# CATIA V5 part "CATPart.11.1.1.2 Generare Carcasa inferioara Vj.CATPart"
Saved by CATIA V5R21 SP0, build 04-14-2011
Part number: Carcasa inferioara VJ I
Bounding box of the stored display mesh (mm): x -120 to 120, y -20 to 190, z -98 to 38
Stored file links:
  C:\Users\MIRCEA\Desktop\MOM\Mogan\model\CATPart.11.1.1.2 Generare Carcasa inferioara Vj.CATPart
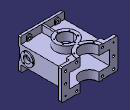
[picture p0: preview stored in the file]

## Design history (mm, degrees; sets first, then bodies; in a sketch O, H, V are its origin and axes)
Parameters
  aw = 100 mm
  a = 90 mm
  Lg = 60 mm
  L1 = 85 mm
  L2 = 75 mm
  Rf1 = 46 mm
  Rr1 = 31 mm
  Rf2 = 55 mm
  Rr2 = 40 mm
  gf1 = 12 mm
  gf2 = 15 mm
  gp = 8 mm
  Lf1 = 35 mm
  Lf = 35 mm
Sketch1 on face of Pad1 from Sketch2.L11, origin (0, -10, 2.4007), H (-1, 0, 0), V (0, 0, 1)
  point P1 (70.0496, -70.1533)
  line L1 (70.0496, -70.1533) -> (50.0496, -70.1533)
  line L2 (70.0496, -70.1533) -> (70.0496, -83.9084)
  point P4 (70.0496, -85.1533)
  line L3 (50.0496, -70.1533) -> (50.0496, -83.9084)
  arc A1 centre (60.0496, -83.9084) radius 10 from (50.0496, -83.9084) to (70.0496, -83.9084) ccw
  line L4 (70.0496, 5.8467) -> (50.0496, 5.8467)
  point P8 (50.0496, 5.8467)
  line L5 (50.0496, 5.8467) -> (50.0496, 19.1827)
  point P9 (50.0496, 20.8467)
  line L6 (70.0496, 5.8467) -> (70.0496, 19.1827)
  arc A2 centre (60.0496, 19.1827) radius 10 from (70.0496, 19.1827) to (50.0496, 19.1827) ccw
  distance P1 P4 = 15
  radius A1 = 10
  distance P8 P9 = 15
  radius A2 = 10
  horizontal: L1 H, L4 H
  vertical: L2 V, L3 V, L5 V, L6 V
  coincidence: L2 P4, P8 L3, L5 P9
  tangency: A1 L3, A1 L2, A2 L6, A2 L5
Sketch2 on yz-plane, origin (0, 0, 0), H (0, 1, 0), V (0, 0, 1)
  point P1 (0, -68)
  line L1 (0, -68) -> (0, 8)
  line L2 (0, 8) -> (-10, 8)
  line L3 (-10, 8) -> (-10, 38)
  line L4 (-10, 38) -> (-20, 38)
  line L5 (-20, 38) -> (-20, -2)
  line L6 (-20, -2) -> (-17, -5)
  line L7 (-17, -5) -> (-17, -55)
  line L8 (-17, -55) -> (-20, -58)
  point P9 (-20, -58)
  line L9 (-20, -58) -> (-20, -98)
  line L10 (-20, -98) -> (-10, -98)
  point P11 (-10, -98)
  line L11 (-10, -98) -> (-10, -68)
  line L12 (-10, -68) -> (0, -68)
  reference intersected line E1 through (0, 0) direction (-1, 0) from xy-plane
  reference intersected line E2 through (0, -30) direction (-1, 0) from Plane1
  reference intersected line E3 through (0, -30) direction (-1, 0) from Plane1
  reference intersected line E4 through (0, -30) direction (-1, 0) from Plane1
  distance L4 L10 = 136 {= Lg + 2*Lf + 6 mm}
  distance L5 L3 = 10
  distance L3 L1 = 10
  distance L7 L5 = 3
  angle L5 L6 = 45
  length L7 = 50
  distance E1 L2 = 8 {= gp}
  coincidence: P1 V, P9 L5, P11 L3
  vertical: L1 V, L3 V, L5 V, L7 V, L9 V, L11 V
  horizontal: L2 H, L4 H, L10 H, L12 H
  symmetry: L12 L2 E2, L4 L10 E3, L8 L6 E4
Pad1 "Talpa": profile Sketch2, direction (1, 0, 0), length 93 {= L1 +gp}, mirrored extent
Set1
  Plane1: type Offset, RefPlane start face of Pad2, Offset 30 {= Lg /2}, reversed
  Plane2: type Offset, RefPlane zx-plane, Offset 190 {= aw+a}
  DatumCurve1
  DatumCurve2
  Sketch3, origin (-120, 217, -71), H (0, 0, -1), V (-1, 0, 0), geometry linked from another document
  DatumCurve3 to DatumCurve8
  DatumSurface1
Body1 (main body)
  Sketch4 on xy-plane, origin (0, 0, 0), H (1, 0, 0), V (0, 1, 0)
    line L1 (85, 190) -> (85, 0)
    point P1 (85, 0)
    line L2 (85, 0) -> (-85, 0)
    circle A1 centre (0, 90) radius 31
    point P2 (0, 90)
    arc A2 centre (0, 190) radius 40 from (-40, 190) to (40, 190) ccw
    point P4 (0, 190)
    line L3 (-85, 0) -> (-85, 190)
    line L4 (-85, 190) -> (-40, 190)
    point P6 (-40, 190)
    line L5 (85, 190) -> (40, 190)
    point P7 (40, 190)
    point P8 (-40, 190)
    point P9 (40, 190)
    construction line L6 (0, 90) -> (0, 190)
    distance P2 L2 = 90 {= a}
    radius A1 = 31 {= Rr1}
    distance P4 L1 = 85 {= L1}
    radius A2 = 40 {= Rr2}
    distance P2 P4 = 100 {= aw}
    coincidence: P1 H, P6 A2, P7 A2, L5 P9, L4 P8, L4 L5, L4 P4
    vertical: L1 V, L3 V, L6 V
    horizontal: L2 H, L4 H, L5 H
    equidistance: L3 L1 P2
    symmetry: L3 L1 V
  Pad2 "Perete lateral": profile Sketch4, direction (0, 0, 1), length 8 {= gp}
  Mirror1: of the body so far, about Plane1
  Sketch5 on zx-plane, origin (0, 0, 0), H (-1, 0, 0), V (0, 0, 1)
    point P1 (85, 8)
    line L1 (85, 8) -> (93, 8)
    line L2 (93, 8) -> (93, -68)
    line L3 (93, -68) -> (85, -68)
    line L4 (85, -68) -> (85, 8)
    point P2 (93, 8)
    point P3 (93, -68)
    point P4 (85, -68)
    reference intersected line E1 through (0, 0) direction (0, -1) from yz-plane
    reference intersected line E2 through (0, 0) direction (-1, 0) from xy-plane
    reference intersected line E3 through (0, -30) direction (-1, 0) from Plane1
    reference intersected line E4 through (0, 0) direction (0, -1) from yz-plane
    point P7 (-85, 8)
    point P8 (-93, 8)
    point P9 (-93, -68)
    point P10 (-85, -68)
    line L5 (-85, 8) -> (-93, 8)
    line L6 (-93, 8) -> (-93, -68)
    line L7 (-93, -68) -> (-85, -68)
    line L8 (-85, -68) -> (-85, 8)
    distance L4 L2 = 8 {= gp}
    distance E1 L4 = 85 {= L1}
    distance L1 E2 = 8 {= gp}
    horizontal: L1 H, L3 H
    vertical: L2 V, L4 V
    symmetry: L1 L3 E3, P1 P7 E4, P2 P8 E4, P3 P9 E4, P4 P10 E4, L1 L5 E4, L2 L6 E4, L3 L7 E4, L4 L8 E4
  Pad3 "Perete": profile Sketch5, direction (0, 1, 0), length 190 {= aw+a}
  Sketch6 on Plane2, origin (0, 190, 0), H (-1, 0, 0), V (0, 0, 1)
    point P1 (-40, 8)
    line L1 (-40, 8) -> (-40, 35)
    point P2 (-40, 35)
    line L2 (-40, 35) -> (-120, 35)
    point P3 (-120, 35)
    line L3 (-120, 35) -> (-120, -95)
    point P4 (-120, -95)
    line L4 (-120, -95) -> (-40, -95)
    point P5 (-40, -95)
    line L5 (-40, -95) -> (-40, -68)
    point P6 (-40, -68)
    line L6 (-40, -68) -> (-93, -68)
    point P7 (-93, -68)
    line L7 (-93, -68) -> (-93, 8)
    point P8 (-93, 8)
    line L8 (-93, 8) -> (-40, 8)
    reference intersected line E1 through (0, 0) direction (0, -1) from yz-plane
    reference intersected line E2 through (0, 0) direction (0, -1) from yz-plane
    reference intersected line E3 through (0, 0) direction (-1, 0) from xy-plane
    reference intersected line E4 through (0, -30) direction (-1, 0) from Plane1
    reference intersected line E5 through (0, -30) direction (-1, 0) from Plane1
    reference intersected line E6 through (0, 0) direction (0, -1) from yz-plane
    point P11 (40, 8)
    point P12 (40, 35)
    point P13 (120, 35)
    point P14 (120, -95)
    point P15 (40, -95)
    point P16 (40, -68)
    point P17 (93, -68)
    point P18 (93, 8)
    line L9 (40, 8) -> (40, 35)
    line L10 (40, 35) -> (120, 35)
    line L11 (120, 35) -> (120, -95)
    line L12 (120, -95) -> (40, -95)
    line L13 (40, -95) -> (40, -68)
    line L14 (40, -68) -> (93, -68)
    line L15 (93, -68) -> (93, 8)
    line L16 (93, 8) -> (40, 8)
    distance E1 L1 = 40 {= Rr2}
    distance E2 L7 = 93 {= L1 +gp}
    distance L7 L3 = 27 {= Lf -gp}
    distance L8 E3 = 8 {= gp}
    distance L8 L2 = 27 {= Lf -gp}
    vertical: L1 V, L3 V, L5 V, L7 V
    horizontal: L2 H, L4 H, L6 H, L8 H
    coincidence: L1 L5
    symmetry: L6 L8 E4, L2 L4 E5, P1 P11 E6, P2 P12 E6, P3 P13 E6, P4 P14 E6, P5 P15 E6, P6 P16 E6, P7 P17 E6, P8 P18 E6, L1 L9 E6, L2 L10 E6, L3 L11 E6, L4 L12 E6, L5 L13 E6, L6 L14 E6, L7 L15 E6, L8 L16 E6
  Pad4 "Flansa": profile Sketch6, direction (0, -1, 0), length 12 {= gf1}
  Sketch7 on xy-plane, origin (0, 0, 0), H (1, 0, 0), V (0, 1, 0)
    line L1 (40, 190) -> (55, 190)
    line L2 (-40, 190) -> (-55, 190)
    arc A1 centre (0, 190) radius 55 from (-55, 190) to (55, 190) ccw
    point P1 (0, 190)
    point P2 (-54.3777, 181.75)
    point P3 (0, 50)
    reference projected point E1 (0, 190) from axis of face of Pad2 from Sketch4.A2
    reference projected line E2 (-40, 190) -> (-85, 190) from edge [face of Mirror1 | face of Pad2]
    reference projected line E3 (85, 190) -> (40, 190) from edge [face of Mirror1 | face of Pad2]
    construction arc A2 centre (0, 240) radius 60 from (-60, 240) to (60, 240) ccw
    arc A3 centre (0, 190) radius 40 from (-40, 190) to (40, 190) ccw
    reference intersected line E4 through (0, 0) direction (0, 1) from yz-plane
    radius A1 = 55 {= Rf2}
    radius A3 = 40 {= Rr2}
    horizontal: L1 H, L2 H
    concentricity: A1 E1, A3 A1
    coincidence: L2 E2, L1 E3, P2 A1, P1 E4
  Pad5 "Flansa iesire": profile Sketch7, direction (0, 0, 1), length 37.5 {= Lf +2.5mm}, deactivated
  Sketch8 on xy-plane, origin (0, 0, 0), H (1, 0, 0), V (0, 1, 0)
    circle A1 centre (0, 90) radius 46
    point P1 (0, 90)
    circle A2 centre (0, 90) radius 31
    reference intersected line E1 through (0, 0) direction (0, 1) from yz-plane
    reference intersected line E2 through (0, 190) direction (-1, 0) from Plane2
    radius A1 = 46 {= Rf1}
    distance E2 P1 = 100 {= aw}
    radius A2 = 31 {= Rr1}
    concentricity: A2 A1
    coincidence: E1 P1
  Pad6 "Flansa intrare": profile Sketch8, direction (0, 0, 1), length 37.5 {= Lf +2.5mm}, deactivated
  Sketch9 on xy-plane, origin (0, 0, 0), H (1, 0, 0), V (0, 1, 0)
    circle A1 centre (0, 90) radius 31
    point P1 (0, 90)
    arc A2 centre (0, 90) radius 46 from (-7.06, 135.455) to (7.06, 135.455) ccw
    reference intersected line E1 through (0, 0) direction (-1, 0) from zx-plane
    arc A3 centre (0, 190) radius 40 from (-40, 190) to (40, 190) ccw
    point P2 (0, 190)
    arc A4 centre (0, 190) radius 55 from (-55, 190) to (-7.06, 135.455) ccw
    line L1 (40, 190) -> (55, 190)
    line L2 (-55, 190) -> (-40, 190)
    reference intersected line E2 through (0, 190) direction (-1, 0) from Plane2
    reference intersected line E3 through (0, 190) direction (-1, 0) from Plane2
    reference intersected line E4 through (0, 190) direction (-1, 0) from Plane2
    point P7 (7.06, 135.455)
    arc A5 centre (0, 190) radius 55 from (7.06, 135.455) to (55, 190) ccw
    radius A1 = 31 {= Rr1}
    distance P1 E1 = 90 {= a}
    radius A2 = 46 {= Rf1}
    radius A3 = 40 {= Rr2}
    radius A4 = 55 {= Rf2}
    coincidence: P1 V, P2 V, L2 E2, E3 L1, P2 E4, A4 P7, A4 A5
    horizontal: L1 H, L2 H
  Pad7 "Flansa combinata": profile Sketch9, direction (0, 0, 1), length 37.5 {= Lf +2.5mm}
  Sketch10 on xy-plane, origin (0, 0, 0), H (1, 0, 0), V (0, 1, 0)
    point P1 (-53.6749, 178)
    line L1 (-53.6749, 178) -> (-75, 178)
    point P2 (-75, 178)
    line L2 (-75, 178) -> (-72.3551, 163)
    point P3 (-72.3551, 163)
    line L3 (-72.3551, 163) -> (-47.9166, 163)
    arc A1 centre (0, 190) radius 55 from (-53.6749, 178) to (-47.9166, 163) ccw
    point P4 (0, 190)
    point P5 (-47.9166, 163)
    reference intersected line E1 through (0, 190) direction (-1, 0) from Plane2
    reference intersected line E2 through (0, 190) direction (-1, 0) from Plane2
    reference intersected line E3 through (0, 0) direction (0, 1) from yz-plane
    reference intersected line E4 through (0, 0) direction (0, 1) from yz-plane
    point P8 (53.6749, 178)
    point P9 (75, 178)
    point P10 (72.3551, 163)
    point P11 (47.9166, 163)
    line L4 (53.6749, 178) -> (75, 178)
    line L5 (75, 178) -> (72.3551, 163)
    line L6 (72.3551, 163) -> (47.9166, 163)
    arc A2 centre (0, 190) radius 55 from (53.6749, 178) to (47.9166, 163) cw
    radius A1 = 55 {= Rf2}
    angle L1 L2 = 80
    distance E2 L1 = 12 {= gf1}
    distance L1 L3 = 15 {= gf2}
    distance P2 E3 = 75 {= L2}
    horizontal: L1 H, L3 H
    coincidence: P4 V, P4 E1
    symmetry: P1 P8 E4, P2 P9 E4, P3 P10 E4, P5 P11 E4, L1 L4 E4, L2 L5 E4, L3 L6 E4, A1 A2 E4
  Pad8 "Intaritura": profile Sketch10, direction (0, 0, 1), length 35 {= Lf}
  Sketch11 on yz-plane, origin (0, 0, 0), H (0, 1, 0), V (0, 0, 1)
    line L1 (136, 35) -> (135, 35)
    point P1 (136, 35)
    point P2 (135, 35)
    distance V P1 = 136 {= a +Rf1}
    distance H P1 = 35 {= Lf}
    distance P2 V = 135 {= a +aw -Rf2}
    distance H P2 = 35 {= Lf}
  Stiffener1: ExtendedProfile Sketch11, ThicknessTop 0, ThicknessValue 8, deactivated
  Sketch12 on yz-plane, origin (0, 0, 0), H (0, 1, 0), V (0, 0, 1)
    line L1 (-10, 37) -> (44, 35)
    point P1 (-10, 37)
    point P2 (44, 35)
    reference intersected line E1 through (0, 0) direction (0, 1) from zx-plane
    reference intersected line E2 through (0, 0) direction (-1, 0) from xy-plane
    reference intersected line E3 through (0, 0) direction (-1, 0) from xy-plane
    reference intersected line E4 through (0, 0) direction (0, 1) from zx-plane
    distance P2 E1 = 44 {= a-Rf1}
    distance E2 P1 = 37 {= Lf +2mm}
    distance E3 P2 = 35 {= Lf}
    distance E4 P1 = 10
  Stiffener2: ExtendedProfile Sketch12, ThicknessTop 0, ThicknessValue 8
  Mirror2 "Mirror": of Pad5, Sketch7, Pad6, Sketch8, Pad7, Sketch9, Pad8, Sketch10, Stiffener1, Sketch11, Stiffener2, Sketch12, about Plane1
  Sketch13 on face of Pad1, origin (-93, 0, 0), H (0, -1, 0), V (0, 0, 1)
    circle A1 centre (-13.9915, -29.8609) radius 14
    point P1 (0, -30.3484)
    radius A1 = 14
    coincidence: A1 P1, P1 V
  Pad9: profile Sketch13, direction (-1, 0, 0), length 4
  Pad10: profile Sketch1, direction (0, 1, 0), length 4
  RectPattern1: of Pad10, direction 1 instances 1, spacing 0, along face of Pad1 from Sketch2.L11, direction 2 instances 2, spacing 120.1, along face of Pad1 from Sketch2.L11
  Sketch14 on end face of Pad10, origin (-60, -6, 17.5), H (1, 0, 0), V (0, 0, -1)
    point P1 (0, 0)
    reference projected point E1 (0, 0) from Sketch26.P1
    coincidence: E1 P1
  Hole1: placed by Sketch14, at (-60, -6, 17.5) direction (0, -1, 0), diameter 10, through (limit type 6)
  Sketch15 on end face of Pad10, origin (0, -6, 0), H (-1, 0, 0), V (0, 0, 1)
    point P1 (60, -77.5)
    point P2 (-60, -77.5)
    point P3 (-60, 17.5)
    distance P1 H = 77.5
    distance P1 V = 60
    distance P2 V = 60
    distance P3 H = 17.5
  UserPattern1: of Hole1, copies 4, at the points of Sketch15
  Sketch16 on end face of Pad9, origin (-97, 0, 0), H (0, -1, 0), V (0, 0, 1)
    circle A1 centre (-13.9915, -29.8609) radius 10
    reference projected circle E1 centre (-13.9915, -29.8609) radius 14 from edge [face of Pad9 from Sketch13.A1 | end face of Pad9]
    reference projected circle E2 centre (-13.9915, -29.8609) radius 14 from edge [face of Pad9 from Sketch13.A1 | end face of Pad9]
    radius A1 = 10
    distance A1 E1 = 4
    distance A1 E2 = 4
  Pocket1: profile Sketch16, direction (1, 0, 0), length 15
  Fillet1: radius 5, on edge [face of Pad4 from Sketch6.L11 | face of Pad8]; edge [face of Pad4 from Sketch6.L3 | face of Mirror2]; edge [face of Mirror2 | face of Pad4 from Sketch6.L11]; edge [face of Pad8 | face of Pad4 from Sketch6.L3]; edge [face of Pad1 from Sketch2.L4 | face of Pad1]; edge [face of Pad1 from Sketch2.L10 | face of Pad1]; edge [face of Pad1 | face of Pad1 from Sketch2.L10]; edge [face of Pad1 | face of Pad1 from Sketch2.L4]
  Chamfer1: length 1, angle 45, on edge [face of Mirror2 | face of Mirror2] (x2)
  Chamfer2: length 1, angle 45, on edge [face of Pad7 | end face of Pad7]; edge [end face of Pad7 | face of Pad7]
  Sketch17 on end face of Pad7, origin (0, 127.5, 37.5), H (1, 0, 0), V (0, 1, 0)
    point P1 (0, 0)
    reference projected point E1 (0, 0) from Sketch25.P1
    coincidence: E1 P1
  Hole2: placed by Sketch17, at (0, 127.5, 37.5) direction (0, 0, -1), diameter 5, depth 10
  Sketch18 on end face of Pad7, origin (0, 0, 37.5), H (1, 0, 0), V (0, 1, 0)
    point P1 (0, 142.5)
    point P2 (41.1362, 166.25)
    point P3 (-41.1362, 166.25)
    point P4 (41.1362, 166.25)
    point P5 (-41.1362, 166.25)
    coincidence: P4 P2, P5 P3
  UserPattern2: of Hole2, copies 4, at the points of Sketch18
  CircPattern1: of Hole2, instances 6, angular step 60 {= 360.0*1 deg/CircPattern1.AngularNumber}, axis from end face of Pad7
  Sketch19 on face of Mirror2, origin (0, 127.5, -97.5), H (1, 0, 0), V (0, -1, 0)
    point P1 (0, 0)
    reference projected point E1 (0, 0) from Sketch24.P1
    coincidence: E1 P1
  Hole3: placed by Sketch19, at (0, 127.5, -97.5) direction (0, 0, 1), diameter 5, depth 10
  Sketch20 on face of Mirror2, origin (0, 0, -97.5), H (1, 0, 0), V (0, -1, 0)
    point P1 (0, -142.5)
    point P2 (41.1362, -166.25)
    point P3 (41.1362, -166.25)
    point P4 (-41.1362, -166.25)
    point P5 (-41.1362, -166.25)
    coincidence: P3 P2, P5 P4
  UserPattern3: of Hole3, copies 4, at the points of Sketch20
  CircPattern2: of Hole3, instances 6, angular step 60 {= 360.0*1 deg/CircPattern2.AngularNumber}, axis from face of Mirror2
  Sketch21 on face of Pad1, origin (93, 0, 0), H (0, 1, 0), V (0, 0, 1)
    circle A1 centre (20, -30) radius 27.5
    radius A1 = 27.5
  Pad11: profile Sketch21, direction (1, 0, 0), length 5
  Sketch22 on end face of Pad11, origin (98, 0, 0), H (0, 1, 0), V (0, 0, 1)
    circle A1 centre (20, -30) radius 15
    radius A1 = 15
  Pocket2: profile Sketch22, direction (-1, 0, 0), through (limit type 6)
  Sketch23 on end face of Pad11, origin (98, 0, 0), H (0, 1, 0), V (0, 0, 1)
    point P1 (2, -30)
  Sketch24 on face of Mirror2, origin (0, 0, -97.5), H (1, 0, 0), V (0, -1, 0)
    point P1 (0, -127.5)
  Sketch25 on end face of Pad7, origin (0, 0, 37.5), H (1, 0, 0), V (0, 1, 0)
    point P1 (0, 127.5)
  Sketch26 on end face of Pad10, origin (0, -6, 0), H (-1, 0, 0), V (0, 0, 1)
    point P1 (60, 17.5)
    point P2 (60, -77.5)
    distance P1 H = 17.5
    distance P1 V = 60
    distance P2 H = 77.5
  Sketch27 on end face of Pad7, origin (0, 0, 37.5), H (1, 0, 0), V (0, 1, 0)
    point P1 (0, 137.5)
  Sketch28 on face of Mirror2, origin (0, 0, -97.5), H (1, 0, 0), V (0, -1, 0)
    point P1 (0, -137.5)
  Sketch29 on face of Mirror2, origin (0, 190, 0), H (-1, 0, 0), V (0, 0, 1)
    point P1 (60, 17.5)
    distance P1 H = 17.5
    distance P1 V = 60
  Sketch30 on face of Mirror2, origin (0, 190, 0), H (-1, 0, 0), V (0, 0, 1)
    point P1 (-102.5, -77.5)
    reference projected line E1 (-120, 35) -> (-120, -95) from edge [face of Pad4 from Sketch6.L3 | face of Mirror2]
    reference projected line E2 (-120, -95) -> (-55, -95) from edge [face of Mirror2 | face of Mirror2]
    distance P1 E1 = 17.5
    distance P1 E2 = 17.5
  Sketch31 on face of Mirror2, origin (85, 190, 0), H (1, 0, 0), V (0, 0, -1)
    point P1 (17.5, 77.5)
    reference projected point E1 (17.5, 77.5) from Sketch30.P1
    coincidence: E1 P1
  Hole4: placed by Sketch31, at (102.5, 190, -77.5) direction (0, -1, 0), diameter 5, depth 10
  Sketch32 on face of Mirror2, origin (0, 190, 0), H (-1, 0, 0), V (0, 0, 1)
    point P1 (102.5, 17.5)
    reference projected line E1 (120, 35) -> (55, 35) from edge [face of Pad8 | face of Mirror2]
    reference projected line E2 (120, -95) -> (120, 35) from edge [face of Pad4 from Sketch6.L11 | face of Mirror2]
    distance P1 E1 = 17.5
    distance E2 P1 = 17.5
  UserPattern4: of Hole4, copies 2, at the points of Sketch32
  Sketch33 on end face of Pad11, origin (98, 43.75, -30.3571), H (0, 1, 0), V (0, 0, 1)
    point P1 (0, 0)
    reference projected point E1 (0, 0) from Sketch38.P1
    coincidence: E1 P1
  Hole5: placed by Sketch33, at (98, 43.75, -30.3571) direction (-1, 0, 0), diameter 5.5, depth 10
  CircPattern3: of Hole5, instances 3, angular step 120 {= 360.0*1 deg/CircPattern3.AngularNumber}, axis from end face of Pad11
  Sketch34 on face of Mirror2, origin (-55, 190, 0), H (1, 0, 0), V (0, 0, -1)
    point P1 (0, 83)
    reference projected point E1 (0, 83) from Sketch37.P1
    coincidence: E1 P1
  Hole6: placed by Sketch34, at (-55, 190, -83) direction (0, -1, 0), diameter 10, through (limit type 6)
  Sketch35 on face of Mirror2, origin (0, 190, 0), H (-1, 0, 0), V (0, 0, 1)
    point P1 (55, 23)
    reference projected line E1 (40, 8) -> (40, 0) from edge [face of Pad7 | face of Mirror2]
    reference projected line E2 (120, 35) -> (55, 35) from edge [face of Pad8 | face of Mirror2]
    point P2 (-55, 23)
    reference projected line E3 (-55, 35) -> (-120, 35) from edge [face of Pad8 | face of Mirror2]
    reference projected line E4 (-40, 0) -> (-40, 8) from edge [face of Pad7 | face of Mirror2]
    point P3 (-55, -83)
    reference projected line E5 (-40, -68) -> (-40, -60) from edge [face of Mirror2 | face of Mirror2]
    reference projected line E6 (-120, -95) -> (-55, -95) from edge [face of Mirror2 | face of Mirror2]
    distance P1 E1 = 15
    distance P1 E2 = 12
    distance P2 E3 = 12
    distance P2 E4 = 15
    distance P3 E5 = 15
    distance P3 E6 = 12
  UserPattern5: of Hole6, copies 4, at the points of Sketch35
  Sketch36 on face of Mirror2, origin (0, 190, 0), H (-1, 0, 0), V (0, 0, 1)
    point P1 (-102.5, -33)
    point P2 (-102.5, 14.5)
    point P3 (102.5, -33)
    point P4 (102.5, -80.5)
    reference projected point E1 (-102.5, -33) from edge of DatumCurve5
    reference projected point E2 (-102.5, 14.5) from edge of DatumCurve6
    reference projected point E3 (102.5, -33) from edge of DatumCurve7
    reference projected point E4 (102.5, -80.5) from edge of DatumCurve8
    distance P1 E1 = 0
    distance P2 E2 = 0
    distance P3 E3 = 0
    distance P4 E4 = 0
  UserPattern6: of Hole6, copies 5, at the points of Sketch36
  Sketch37 on face of Mirror2, origin (0, 190, 0), H (-1, 0, 0), V (0, 0, 1)
    point P1 (55, -83)
    reference projected line E1 (40, -60) -> (40, -68) from edge [face of Mirror2 | face of Mirror2]
    reference projected line E2 (55, -95) -> (120, -95) from edge [face of Mirror2 | face of Mirror2]
    distance P1 E1 = 15
    distance E2 P1 = 12
  Sketch38 on end face of Pad11, origin (98, 0, 0), H (0, 1, 0), V (0, 0, 1)
    point P1 (43.75, -30.3571)
Body2
  Solid1: solid without history
Relations
  rule "Dezactivare intarituri":
    /*Rule created by BEV 23.04.2020*/
    if aw <= (Rf1 +Rf2 ) Stiffener1.Activity = false
    	else Stiffener1.Activity = true
  rule "Dezactivare Flansa":
    /*Rule created by BEV 24.04.2020*/
    if aw < (Rf1 +Rf2 )
    {
    	Pad5.Activity  = false
    	 Pad6.Activity=false
    	 Pad7.Activity=true
    	 Sketch9.Activity=true
    }
    else
    {
    	Pad5.Activity  = true
    	 Pad6.Activity=true
    	 Pad7.Activity=false
    	 Sketch9.Activity=false
    }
